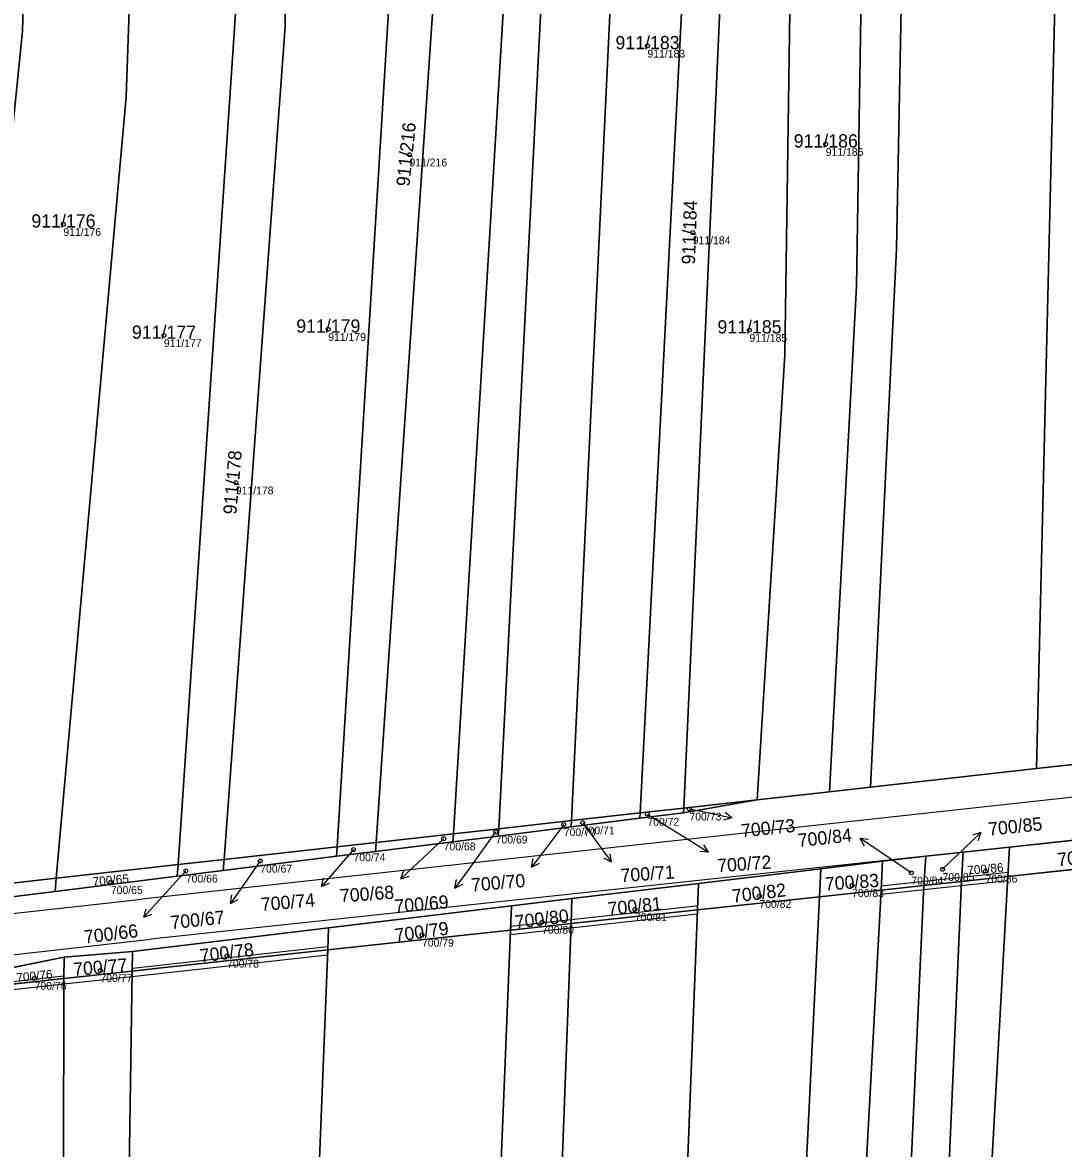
# Model space of a CAD drawing. Extents: x -603967 to -594699, y -1179315 to -1165625.
# Drawn here: x -596555.4 to -596421.9, y -1172077.4 to -1171933.1 of the extents above; entities that cross this region are included whole.
import ezdxf

# ---------------------------------------------------------------- set-up
doc = ezdxf.new("R2010")
doc.units = 0
for name, color, linetype in [('Definiční body', 7, 'Continuous'), ('Hranice parcel', 7, 'Continuous'), ('Parcelní čísla', 7, 'Continuous'), ('Polygon parcely', 7, 'Continuous'), ('Pop  PČ popisy', 7, 'Continuous'), ('Vnitřní kresba', 7, 'Continuous'), ('Věcná břemena k části', 7, 'Continuous')]:
    doc.layers.add(name, color=color, linetype=linetype)

msp = doc.modelspace()

# ---------------------------------------------------------------- linework, layer by layer
at = {"layer": 'Definiční body'}
for centre in [(-596475.23, -1171936.05994), (-596452.37, -1171948.65994), (-596505.75, -1171950.00994), (-596550.12, -1171958.91994), (-596469.42, -1171959.98994), (-596537.23, -1171973.17994), (-596516.16, -1171972.38994), (-596462.15, -1171972.49994), (-596528.01, -1171992.05994), (-596469.84, -1172033.86994), (-596483.52, -1172035.64994), (-596475.24, -1172034.53994), (-596494.69, -1172036.81994), (-596485.96, -1172035.86994), (-596501.36, -1172037.69994), (-596512.92, -1172039.08994), (-596524.88, -1172040.54994), (-596534.42, -1172041.81994), (-596441.39, -1172042.06994), (-596437.39, -1172041.61994), (-596431.88, -1172041.84994), (-596544.03, -1172043.28994), (-596448.99, -1172043.67994), (-596460.88, -1172045.06994), (-596476.83, -1172046.75994), (-596488.74, -1172048.38994), (-596504.14, -1172050.03994), (-596529.13, -1172052.71994), (-596553.81, -1172055.56994), (-596545.37, -1172054.57994)]:
    msp.add_circle(centre, 0.25, dxfattribs=at)
at = {"layer": 'Hranice parcel'}
for p, q in [((-596425.36, -1172028.7), (-596412.58, -1172027.27)), ((-596446.64, -1172031.08), (-596425.36, -1172028.7)), ((-596451.9, -1172031.67), (-596446.64, -1172031.08)), ((-596461.17, -1172032.71), (-596451.9, -1172031.67)), ((-596470.58, -1172033.76), (-596476.18, -1172034.39)), ((-596470.61, -1172034.38), (-596461.17, -1172032.71)), ((-596470.61, -1172034.38), (-596470.58, -1172033.76)), ((-596461.17, -1172032.71), (-596470.58, -1172033.76)), ((-596484.95, -1172035.37), (-596494.3, -1172036.41)), ((-596484.99, -1172036.18), (-596476.22, -1172035.08)), ((-596484.99, -1172036.18), (-596484.95, -1172035.37)), ((-596476.18, -1172034.39), (-596484.95, -1172035.37)), ((-596476.22, -1172035.08), (-596470.61, -1172034.38)), ((-596476.22, -1172035.08), (-596476.18, -1172034.39)), ((-596494.3, -1172036.41), (-596500.1, -1172037.06)), ((-596494.35, -1172037.35), (-596484.99, -1172036.18)), ((-596494.35, -1172037.35), (-596494.3, -1172036.41)), ((-596406.18, -1172036.33), (-596428.79, -1172038.76)), ((-596510.01, -1172038.17), (-596515.01, -1172038.73)), ((-596510.09, -1172039.32), (-596500.16, -1172038.08)), ((-596510.01, -1172038.17), (-596510.09, -1172039.32)), ((-596500.1, -1172037.06), (-596510.01, -1172038.17)), ((-596500.16, -1172038.08), (-596500.1, -1172037.06)), ((-596500.16, -1172038.08), (-596494.35, -1172037.35)), ((-596515.01, -1172038.73), (-596529.52, -1172040.35)), ((-596515.08, -1172039.95), (-596515.01, -1172038.73)), ((-596515.08, -1172039.95), (-596510.09, -1172039.32)), ((-596434.74, -1172039.4), (-596439.55, -1172039.92)), ((-596434.97, -1172043.17), (-596434.74, -1172039.4)), ((-596428.79, -1172038.76), (-596434.74, -1172039.4)), ((-596429, -1172042.53), (-596428.79, -1172038.76)), ((-596535.51, -1172042.51), (-596535.41, -1172041.01)), ((-596529.52, -1172040.35), (-596535.41, -1172041.01)), ((-596529.62, -1172041.77), (-596515.08, -1172039.95)), ((-596529.62, -1172041.77), (-596529.52, -1172040.35)), ((-596445.07, -1172040.59), (-596453, -1172041.54)), ((-596445.27, -1172044.28), (-596445.07, -1172040.59)), ((-596439.55, -1172039.92), (-596445.07, -1172040.59)), ((-596439.77, -1172043.69), (-596439.55, -1172039.92)), ((-596429, -1172042.53), (-596406.35, -1172040.08)), ((-596551.18, -1172044.47), (-596535.51, -1172042.51)), ((-596535.51, -1172042.51), (-596529.62, -1172041.77)), ((-596453, -1172041.54), (-596468.66, -1172043.42)), ((-596453.18, -1172045.14), (-596453, -1172041.54)), ((-596434.97, -1172043.17), (-596429, -1172042.53)), ((-596551.03, -1172042.76), (-596566.55, -1172044.51)), ((-596551.18, -1172044.47), (-596551.03, -1172042.76)), ((-596468.66, -1172043.42), (-596484.91, -1172045.37)), ((-596468.79, -1172046.83), (-596468.66, -1172043.42)), ((-596445.27, -1172044.28), (-596439.77, -1172043.69)), ((-596439.77, -1172043.69), (-596434.97, -1172043.17)), ((-596566.74, -1172046.38), (-596551.18, -1172044.47)), ((-596484.91, -1172045.37), (-596492.64, -1172046.3)), ((-596485.02, -1172048.58), (-596484.91, -1172045.37)), ((-596468.79, -1172046.83), (-596453.18, -1172045.14)), ((-596453.18, -1172045.14), (-596445.27, -1172044.28)), ((-596492.64, -1172046.3), (-596516.14, -1172049.12)), ((-596492.77, -1172049.42), (-596492.64, -1172046.3)), ((-596485.02, -1172048.58), (-596468.79, -1172046.83)), ((-596480.31, -1172340.97), (-596468.79, -1172046.83)), ((-596516.14, -1172049.12), (-596541.24, -1172052.14)), ((-596516.23, -1172051.95), (-596516.14, -1172049.12)), ((-596516.23, -1172051.95), (-596492.77, -1172049.42)), ((-596492.77, -1172049.42), (-596485.02, -1172048.58)), ((-596541.24, -1172052.14), (-596550.02, -1172052.87)), ((-596541.28, -1172054.66), (-596541.24, -1172052.14)), ((-596550.02, -1172052.87), (-596567.38, -1172056.37)), ((-596550.05, -1172055.61), (-596550.02, -1172052.87)), ((-596567.38, -1172057.49), (-596550.05, -1172055.61)), ((-596550.05, -1172055.61), (-596541.28, -1172054.66)), ((-596545.5, -1172332.42), (-596541.28, -1172054.66))]:
    msp.add_line(p, q, dxfattribs=at)
for points in [[(-596425.36, -1172028.7), (-596422.7, -1171918.33), (-596423.77, -1171871.67), (-596425.5, -1171841.17), (-596427.65, -1171811.28)], [(-596446.64, -1172031.08), (-596443.31, -1171962.07), (-596442.12, -1171902.47), (-596443.19, -1171867.2), (-596445.72, -1171822.04)], [(-596451.9, -1172031.67), (-596448.43, -1171966.84), (-596447.49, -1171908), (-596450.36, -1171824.81)], [(-596461.17, -1172032.71), (-596457.62, -1171975.67), (-596456.78, -1171919.78), (-596459.56, -1171829.63)], [(-596470.58, -1172033.76), (-596465.37, -1171919.02), (-596468.45, -1171834.29)], [(-596476.18, -1172034.39), (-596470.14, -1171917.71), (-596473.01, -1171836.27)], [(-596484.95, -1172035.37), (-596479.49, -1171920.38), (-596481.35, -1171839.89)], [(-596494.3, -1172036.41), (-596488.36, -1171920.51), (-596489.5, -1171843.43)], [(-596500.1, -1172037.06), (-596493.15, -1171922.52), (-596494.76, -1171845.71)], [(-596504.12, -1171849.77), (-596502.17, -1171923.09), (-596510.01, -1172038.17)], [(-596515.01, -1172038.73), (-596507.68, -1171919.03), (-596508.95, -1171851.87)], [(-596529.52, -1172040.35), (-596521.69, -1171933.58), (-596521.33, -1171857.24)], [(-596535.41, -1172041.01), (-596527.65, -1171926.15), (-596526.52, -1171859.49)], [(-596551.03, -1172042.76), (-596542.08, -1171942.58), (-596539.38, -1171865.07)], [(-596566.55, -1172044.51), (-596555.36, -1171934.18), (-596553.65, -1171870.92)], [(-596535.41, -1172041.01), (-596539.55, -1172041.47), (-596551.03, -1172042.76)], [(-596443.43, -1172344.03), (-596438.52, -1172212.57), (-596429, -1172042.53)], [(-596454.62, -1172343.1), (-596447.98, -1172182.42), (-596443.84, -1172132.82), (-596439.77, -1172043.69)], [(-596448.65, -1172343.6), (-596442.7, -1172172.73), (-596438.88, -1172133.03), (-596434.97, -1172043.17)], [(-596466.35, -1172342.13), (-596459.87, -1172181.54), (-596453.18, -1172045.14)], [(-596459.45, -1172342.7), (-596452.82, -1172183.74), (-596445.27, -1172044.28)], [(-596502.08, -1172339.16), (-596498.32, -1172185.67), (-596492.77, -1172049.42)], [(-596494.69, -1172339.77), (-596488.9, -1172152.4), (-596485.02, -1172048.58)], [(-596541.28, -1172054.66), (-596537.94, -1172054.3), (-596516.23, -1172051.95)], [(-596525.15, -1172335.58), (-596520.23, -1172152.75), (-596516.23, -1172051.95)], [(-596553.66, -1172331.15), (-596552.65, -1172290.86), (-596550.23, -1172154.62), (-596550.05, -1172055.61)]]:
    msp.add_lwpolyline(points, dxfattribs=at)
at = {"layer": 'Polygon parcely'}
for points in [[(-596425.36, -1172028.7), (-596412.58, -1172027.27), (-596410.12, -1171947.89), (-596411.59, -1171885.32), (-596416.84, -1171804.76), (-596427.65, -1171811.28), (-596425.5, -1171841.17), (-596423.77, -1171871.67), (-596422.7, -1171918.33)], [(-596446.64, -1172031.08), (-596425.36, -1172028.7), (-596422.7, -1171918.33), (-596423.77, -1171871.67), (-596425.5, -1171841.17), (-596427.65, -1171811.28), (-596445.72, -1171822.04), (-596443.19, -1171867.2), (-596442.12, -1171902.47), (-596443.31, -1171962.07)], [(-596451.9, -1172031.67), (-596446.64, -1172031.08), (-596443.31, -1171962.07), (-596442.12, -1171902.47), (-596443.19, -1171867.2), (-596445.72, -1171822.04), (-596450.36, -1171824.81), (-596447.49, -1171908), (-596448.43, -1171966.84)], [(-596461.17, -1172032.71), (-596451.9, -1172031.67), (-596448.43, -1171966.84), (-596447.49, -1171908), (-596450.36, -1171824.81), (-596459.56, -1171829.63), (-596456.78, -1171919.78), (-596457.62, -1171975.67)], [(-596461.17, -1172032.71), (-596457.62, -1171975.67), (-596456.78, -1171919.78), (-596459.56, -1171829.63), (-596468.45, -1171834.29), (-596465.37, -1171919.02), (-596470.58, -1172033.76)], [(-596465.37, -1171919.02), (-596468.45, -1171834.29), (-596473.01, -1171836.27), (-596470.14, -1171917.71), (-596476.18, -1172034.39), (-596470.58, -1172033.76)], [(-596476.18, -1172034.39), (-596470.14, -1171917.71), (-596473.01, -1171836.27), (-596481.35, -1171839.89), (-596479.49, -1171920.38), (-596484.95, -1172035.37)], [(-596484.95, -1172035.37), (-596479.49, -1171920.38), (-596481.35, -1171839.89), (-596489.5, -1171843.43), (-596488.36, -1171920.51), (-596494.3, -1172036.41)], [(-596488.36, -1171920.51), (-596489.5, -1171843.43), (-596494.76, -1171845.71), (-596493.15, -1171922.52), (-596500.1, -1172037.06), (-596494.3, -1172036.41)], [(-596510.01, -1172038.17), (-596500.1, -1172037.06), (-596493.15, -1171922.52), (-596494.76, -1171845.71), (-596504.12, -1171849.77), (-596502.17, -1171923.09)], [(-596515.01, -1172038.73), (-596510.01, -1172038.17), (-596502.17, -1171923.09), (-596504.12, -1171849.77), (-596508.95, -1171851.87), (-596507.68, -1171919.03)], [(-596515.01, -1172038.73), (-596507.68, -1171919.03), (-596508.95, -1171851.87), (-596521.33, -1171857.24), (-596521.69, -1171933.58), (-596529.52, -1172040.35)], [(-596529.52, -1172040.35), (-596521.69, -1171933.58), (-596521.33, -1171857.24), (-596526.52, -1171859.49), (-596527.65, -1171926.15), (-596535.41, -1172041.01)], [(-596535.41, -1172041.01), (-596527.65, -1171926.15), (-596526.52, -1171859.49), (-596539.38, -1171865.07), (-596542.08, -1171942.58), (-596551.03, -1172042.76), (-596539.55, -1172041.47)], [(-596542.08, -1171942.58), (-596539.38, -1171865.07), (-596553.65, -1171870.92), (-596555.36, -1171934.18), (-596566.55, -1172044.51), (-596551.03, -1172042.76)], [(-596555.36, -1171934.18), (-596553.65, -1171870.92), (-596560.55, -1171874.7), (-596561.86, -1171929.91), (-596567.32, -1171984.12), (-596574.3, -1172045.38), (-596566.55, -1172044.51)], [(-596470.61, -1172034.38), (-596470.58, -1172033.76), (-596476.18, -1172034.39), (-596476.22, -1172035.08)], [(-596461.17, -1172032.71), (-596470.58, -1172033.76), (-596470.61, -1172034.38)], [(-596484.99, -1172036.18), (-596484.95, -1172035.37), (-596494.3, -1172036.41), (-596494.35, -1172037.35)], [(-596476.22, -1172035.08), (-596476.18, -1172034.39), (-596484.95, -1172035.37), (-596484.99, -1172036.18)], [(-596494.35, -1172037.35), (-596494.3, -1172036.41), (-596500.1, -1172037.06), (-596500.16, -1172038.08)], [(-596428.79, -1172038.76), (-596429, -1172042.53), (-596406.35, -1172040.08), (-596406.18, -1172036.33)], [(-596510.09, -1172039.32), (-596510.01, -1172038.17), (-596515.01, -1172038.73), (-596515.08, -1172039.95)], [(-596500.16, -1172038.08), (-596500.1, -1172037.06), (-596510.01, -1172038.17), (-596510.09, -1172039.32)], [(-596515.08, -1172039.95), (-596515.01, -1172038.73), (-596529.52, -1172040.35), (-596529.62, -1172041.77)], [(-596439.55, -1172039.92), (-596439.77, -1172043.69), (-596434.97, -1172043.17), (-596434.74, -1172039.4)], [(-596434.74, -1172039.4), (-596434.97, -1172043.17), (-596429, -1172042.53), (-596428.79, -1172038.76)], [(-596551.18, -1172044.47), (-596535.51, -1172042.51), (-596535.41, -1172041.01), (-596539.55, -1172041.47), (-596551.03, -1172042.76)], [(-596529.62, -1172041.77), (-596529.52, -1172040.35), (-596535.41, -1172041.01), (-596535.51, -1172042.51)], [(-596445.07, -1172040.59), (-596453, -1172041.54), (-596453.18, -1172045.14), (-596445.27, -1172044.28)], [(-596439.55, -1172039.92), (-596445.07, -1172040.59), (-596445.27, -1172044.28), (-596439.77, -1172043.69)], [(-596420.62, -1172345.93), (-596406.35, -1172040.08), (-596429, -1172042.53), (-596438.52, -1172212.57), (-596443.43, -1172344.03)], [(-596453, -1172041.54), (-596468.66, -1172043.42), (-596468.79, -1172046.83), (-596453.18, -1172045.14)], [(-596443.43, -1172344.03), (-596438.52, -1172212.57), (-596429, -1172042.53), (-596434.97, -1172043.17), (-596438.88, -1172133.03), (-596442.7, -1172172.73), (-596448.65, -1172343.6)], [(-596566.74, -1172046.38), (-596551.18, -1172044.47), (-596551.03, -1172042.76), (-596566.55, -1172044.51)], [(-596468.66, -1172043.42), (-596484.91, -1172045.37), (-596485.02, -1172048.58), (-596468.79, -1172046.83)], [(-596454.62, -1172343.1), (-596447.98, -1172182.42), (-596443.84, -1172132.82), (-596439.77, -1172043.69), (-596445.27, -1172044.28), (-596452.82, -1172183.74), (-596459.45, -1172342.7)], [(-596438.88, -1172133.03), (-596434.97, -1172043.17), (-596439.77, -1172043.69), (-596443.84, -1172132.82), (-596447.98, -1172182.42), (-596454.62, -1172343.1), (-596448.65, -1172343.6), (-596442.7, -1172172.73)], [(-596484.91, -1172045.37), (-596492.64, -1172046.3), (-596492.77, -1172049.42), (-596485.02, -1172048.58)], [(-596459.87, -1172181.54), (-596453.18, -1172045.14), (-596468.79, -1172046.83), (-596480.31, -1172340.97), (-596466.35, -1172342.13)], [(-596459.45, -1172342.7), (-596452.82, -1172183.74), (-596445.27, -1172044.28), (-596453.18, -1172045.14), (-596459.87, -1172181.54), (-596466.35, -1172342.13)], [(-596492.64, -1172046.3), (-596516.14, -1172049.12), (-596516.23, -1172051.95), (-596492.77, -1172049.42)], [(-596480.31, -1172340.97), (-596468.79, -1172046.83), (-596485.02, -1172048.58), (-596488.9, -1172152.4), (-596494.69, -1172339.77)], [(-596516.14, -1172049.12), (-596541.24, -1172052.14), (-596541.28, -1172054.66), (-596537.94, -1172054.3), (-596516.23, -1172051.95)], [(-596502.08, -1172339.16), (-596498.32, -1172185.67), (-596492.77, -1172049.42), (-596516.23, -1172051.95), (-596520.23, -1172152.75), (-596525.15, -1172335.58)], [(-596494.69, -1172339.77), (-596488.9, -1172152.4), (-596485.02, -1172048.58), (-596492.77, -1172049.42), (-596498.32, -1172185.67), (-596502.08, -1172339.16)], [(-596541.24, -1172052.14), (-596550.02, -1172052.87), (-596550.05, -1172055.61), (-596541.28, -1172054.66)], [(-596520.23, -1172152.75), (-596516.23, -1172051.95), (-596537.94, -1172054.3), (-596541.28, -1172054.66), (-596545.5, -1172332.42), (-596525.15, -1172335.58)], [(-596550.02, -1172052.87), (-596567.38, -1172056.37), (-596567.38, -1172057.49), (-596550.05, -1172055.61)], [(-596553.66, -1172331.15), (-596552.65, -1172290.86), (-596550.23, -1172154.62), (-596550.05, -1172055.61), (-596567.38, -1172057.49), (-596566.39, -1172235.48), (-596569.05, -1172328.76)], [(-596545.5, -1172332.42), (-596541.28, -1172054.66), (-596550.05, -1172055.61), (-596550.23, -1172154.62), (-596552.65, -1172290.86), (-596553.66, -1172331.15)]]:
    msp.add_lwpolyline(points, close=True, dxfattribs=at)
for points in [[(-596412.58, -1172027.27), (-596425.36, -1172028.7), (-596446.64, -1172031.08), (-596451.9, -1172031.67), (-596461.17, -1172032.71), (-596470.61, -1172034.38), (-596476.22, -1172035.08), (-596484.99, -1172036.18), (-596494.35, -1172037.35), (-596500.16, -1172038.08), (-596510.09, -1172039.32), (-596515.08, -1172039.95), (-596529.62, -1172041.77), (-596535.51, -1172042.51), (-596551.18, -1172044.47), (-596566.74, -1172046.38)], [(-596567.38, -1172056.37), (-596550.02, -1172052.87), (-596541.24, -1172052.14), (-596516.14, -1172049.12), (-596492.64, -1172046.3), (-596484.91, -1172045.37), (-596468.66, -1172043.42), (-596453, -1172041.54), (-596445.07, -1172040.59), (-596439.55, -1172039.92), (-596434.74, -1172039.4), (-596428.79, -1172038.76), (-596406.18, -1172036.33)]]:
    msp.add_lwpolyline(points, dxfattribs=at)
at = {"layer": 'Pop  PČ popisy'}
for p, q in [((-596469.84, -1172033.87), (-596467.34, -1172034.39)), ((-596475.24, -1172034.54), (-596469.94, -1172037.85)), ((-596467.34, -1172034.39), (-596464.405, -1172035.014)), ((-596464.405, -1172035.014), (-596465.488, -1172035.296)), ((-596464.405, -1172035.014), (-596465.28, -1172034.316)), ((-596494.69, -1172036.82), (-596498.15, -1172041.62)), ((-596485.96, -1172035.87), (-596488.27, -1172038.93)), ((-596483.52, -1172035.65), (-596481.58, -1172038.29)), ((-596501.36, -1172037.7), (-596504.66, -1172040.78)), ((-596481.58, -1172038.29), (-596479.816, -1172040.718)), ((-596469.94, -1172037.85), (-596467.395, -1172039.44)), ((-596445.52, -1172039.29), (-596448.008, -1172037.612)), ((-596448.008, -1172037.612), (-596446.898, -1172037.757)), ((-596448.008, -1172037.612), (-596447.458, -1172038.587)), ((-596434.65, -1172038.98), (-596432.491, -1172036.895)), ((-596432.491, -1172036.895), (-596433.56, -1172037.231)), ((-596432.491, -1172036.895), (-596432.864, -1172037.951)), ((-596512.92, -1172039.09), (-596515.07, -1172041.56)), ((-596488.27, -1172038.93), (-596490.076, -1172041.327)), ((-596479.816, -1172040.718), (-596480, -1172039.613)), ((-596467.395, -1172039.44), (-596468.51, -1172039.334)), ((-596467.395, -1172039.44), (-596467.979, -1172038.485)), ((-596441.39, -1172042.07), (-596445.52, -1172039.29)), ((-596437.39, -1172041.62), (-596434.65, -1172038.98)), ((-596524.88, -1172040.55), (-596526.96, -1172043.55)), ((-596504.66, -1172040.78), (-596506.855, -1172042.827)), ((-596490.076, -1172041.327), (-596489.873, -1172040.226)), ((-596490.076, -1172041.327), (-596489.073, -1172040.828)), ((-596479.816, -1172040.718), (-596480.81, -1172040.202)), ((-596534.42, -1172041.82), (-596537.79, -1172045.54)), ((-596515.07, -1172041.56), (-596517.039, -1172043.825)), ((-596506.855, -1172042.827), (-596506.464, -1172041.777)), ((-596506.855, -1172042.827), (-596505.781, -1172042.51)), ((-596498.15, -1172041.62), (-596499.914, -1172044.048)), ((-596526.96, -1172043.55), (-596528.681, -1172046.008)), ((-596517.039, -1172043.825), (-596516.76, -1172042.741)), ((-596517.039, -1172043.825), (-596516.004, -1172043.398)), ((-596499.914, -1172044.048), (-596499.73, -1172042.943)), ((-596499.914, -1172044.048), (-596498.92, -1172043.532)), ((-596528.681, -1172046.008), (-596528.517, -1172044.901)), ((-596528.681, -1172046.008), (-596527.697, -1172045.475)), ((-596537.79, -1172045.54), (-596539.798, -1172047.77)), ((-596539.798, -1172047.77), (-596539.5, -1172046.691)), ((-596539.798, -1172047.77), (-596538.756, -1172047.361))]:
    msp.add_line(p, q, dxfattribs=at)
at = {"layer": 'Vnitřní kresba'}
for p, q in [((-596257.94, -1172014.51), (-596540.04, -1172045.45)), ((-596439.55, -1172039.92), (-596538.9, -1172050.58)), ((-596705.84, -1172063.76), (-596540.04, -1172045.45)), ((-596700.13, -1172068.83), (-596538.9, -1172050.58))]:
    msp.add_line(p, q, dxfattribs=at)
at = {"layer": 'Věcná břemena k části'}
for points in [[(-596429.03, -1172043.04), (-596429, -1172042.53), (-596428.97, -1172042.03), (-596434.94, -1172042.67), (-596434.97, -1172043.17), (-596434.99, -1172043.68)], [(-596445.24, -1172043.78), (-596445.27, -1172044.28), (-596445.3, -1172044.79), (-596439.79, -1172044.2), (-596439.77, -1172043.69), (-596439.74, -1172043.19)], [(-596439.74, -1172043.19), (-596439.77, -1172043.69), (-596439.79, -1172044.2), (-596434.99, -1172043.68), (-596434.97, -1172043.17), (-596434.94, -1172042.67)], [(-596485, -1172048.11), (-596485.02, -1172048.58), (-596485.04, -1172049.12), (-596469.63, -1172047.41), (-596468.81, -1172047.32), (-596468.79, -1172046.83), (-596468.77, -1172046.32), (-596469.74, -1172046.42)], [(-596492.75, -1172048.96), (-596492.77, -1172049.42), (-596492.79, -1172049.97), (-596485.04, -1172049.12), (-596485.02, -1172048.58), (-596485, -1172048.11)], [(-596541.27, -1172054.33), (-596541.28, -1172054.66), (-596541.29, -1172055.34), (-596516.25, -1172052.57), (-596516.23, -1172051.95), (-596516.22, -1172051.56)], [(-596567.38, -1172057.23), (-596567.38, -1172057.49), (-596567.38, -1172058.23), (-596550.05, -1172056.31), (-596550.05, -1172055.61), (-596550.05, -1172055.31)], [(-596550.05, -1172056.31), (-596541.29, -1172055.34), (-596541.28, -1172054.66), (-596550.05, -1172055.61)]]:
    msp.add_lwpolyline(points, close=True, dxfattribs=at)

# ---------------------------------------------------------------- texts
at = {"layer": 'Definiční body'}
for s, p in [('911/183', (-596475.23, -1171937.549)), ('911/186', (-596452.37, -1171950.149)), ('911/216', (-596505.75, -1171951.499)), ('911/176', (-596550.12, -1171960.409)), ('911/184', (-596469.42, -1171961.479)), ('911/179', (-596516.16, -1171973.879)), ('911/185', (-596462.15, -1171973.989)), ('911/177', (-596537.23, -1171974.669)), ('911/178', (-596528.01, -1171993.549)), ('700/72', (-596475.24, -1172036.029)), ('700/73', (-596469.84, -1172035.359)), ('700/70', (-596485.96, -1172037.359)), ('700/71', (-596483.52, -1172037.139)), ('700/68', (-596501.36, -1172039.189)), ('700/69', (-596494.69, -1172038.309)), ('700/74', (-596512.92, -1172040.579)), ('700/67', (-596524.88, -1172042.039)), ('700/66', (-596534.42, -1172043.309)), ('700/84', (-596441.39, -1172043.559)), ('700/85', (-596437.39, -1172043.109)), ('700/86', (-596431.88, -1172043.339)), ('700/65', (-596544.03, -1172044.779)), ('700/82', (-596460.88, -1172046.559)), ('700/83', (-596448.99, -1172045.169)), ('700/81', (-596476.83, -1172048.249)), ('700/80', (-596488.74, -1172049.879)), ('700/79', (-596504.14, -1172051.529)), ('700/78', (-596529.13, -1172054.209)), ('700/77', (-596545.37, -1172056.069)), ('700/76', (-596553.81, -1172057.059))]:
    msp.add_text(s, height=0.999996, dxfattribs=at).set_placement(p)
at = {"layer": 'Parcelní čísla'}
for s, p in [('911/183', (-596479.326, -1171936.485)), ('911/186', (-596456.466, -1171949.085)), ('911/176', (-596554.216, -1171959.345)), ('911/177', (-596541.326, -1171973.605)), ('911/179', (-596520.256, -1171972.815)), ('911/185', (-596466.246, -1171972.925))]:
    msp.add_text(s, height=1.699998, dxfattribs=at).set_placement(p)
for s, height, rotation, p in [('911/216', 1.699998, 84, (-596505.755, -1171954.128)), ('911/184', 1.699998, 87.9999972, (-596469.138, -1171964.099)), ('911/178', 1.699998, 85, (-596527.943, -1171996.178)), ('700/73', 1.699998, 6, (-596463.131, -1172037.541)), ('700/85', 1.699998, 6, (-596431.445, -1172037.322)), ('700/84', 1.699998, 6, (-596455.86, -1172038.767)), ('700/87', 1.699998, 6, (-596422.592, -1172041.235)), ('700/71', 1.699998, 4, (-596478.621, -1172043.269)), ('700/72', 1.699998, 4, (-596466.221, -1172041.999)), ('700/86', 1.14, 5, (-596434.17, -1172042.336)), ('700/65', 1.14, 5, (-596546.32, -1172043.776)), ('700/70', 1.699998, 5, (-596497.762, -1172044.479)), ('700/83', 1.699998, 4, (-596452.418, -1172044.345)), ('700/68', 1.699998, 4, (-596514.596, -1172045.862)), ('700/82', 1.699998, 7, (-596464.268, -1172045.914)), ('700/74', 1.699998, 5, (-596524.722, -1172046.979)), ('700/69', 1.699998, 5, (-596507.592, -1172047.209)), ('700/81', 1.699998, 6, (-596480.232, -1172047.545)), ('700/67', 1.699998, 6, (-596536.296, -1172049.296)), ('700/80', 1.699998, 7, (-596492.128, -1172049.234)), ('700/79', 1.699998, 8, (-596507.513, -1172050.943)), ('700/66', 1.699998, 7, (-596547.368, -1172051.151)), ('700/78', 1.699998, 7, (-596532.518, -1172053.564)), ('700/77', 1.699998, 5, (-596548.786, -1172055.305)), ('700/76', 1.14, 6, (-596556.092, -1172056.096))]:
    msp.add_text(s, height=height, rotation=rotation, dxfattribs=at).set_placement(p)

doc.saveas('drawing.dxf')
